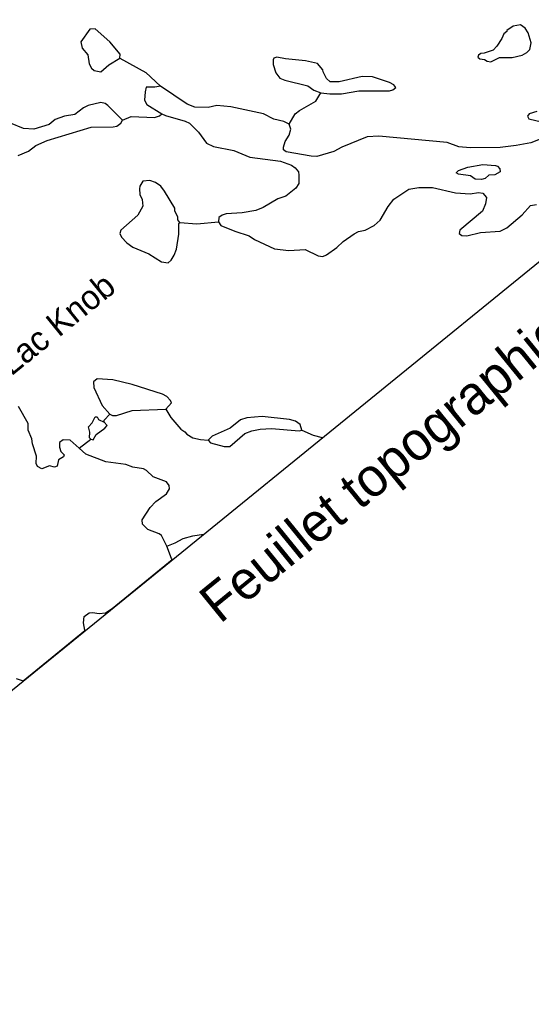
# Model space of a CAD drawing. Extents: x 347059 to 352153, y 6073752 to 6078601.
# Drawn here: x 351007.8 to 351123.8, y 6077139.1 to 6077359.2 of the extents above; entities that cross this region are included whole.
import ezdxf

# ---------------------------------------------------------------- set-up
doc = ezdxf.new("R2010")
doc.units = 0
doc.layers.add('Level 63', color=7, linetype='Continuous')

msp = doc.modelspace()

# ---------------------------------------------------------------- linework, layer by layer
at = {"layer": 'Level 63'}
msp.add_line((351021.38, 6077262.12), (351024, 6077264.16), dxfattribs=at)
msp.add_lwpolyline([(350822.11, 6077057.72), (351218.14, 6077379.8), (350976.59, 6077676.83), (350580.55, 6077354.75)], close=True, dxfattribs=at)
for points in [[(351030.57, 6077350.38), (351030.64, 6077351.32), (351028.25, 6077354.08), (351024.94, 6077357.08), (351023.75, 6077356.96), (351021.75, 6077354.11), (351022.03, 6077352.71), (351023.34, 6077351.14), (351023.63, 6077349.1), (351024.15, 6077348.13), (351024.72, 6077347.61), (351026.23, 6077347.33), (351028.06, 6077348.92), (351030.57, 6077350.38)], [(351119.6, 6077357.65), (351118.16, 6077356.69), (351118.13, 6077356.42), (351117.52, 6077355.95), (351117.07, 6077354.87), (351115.9, 6077353.15), (351115.06, 6077352.26), (351113.06, 6077351.51), (351112.28, 6077351.47), (351111.77, 6077351.08), (351111.58, 6077350.6), (351112.03, 6077350.23), (351113.11, 6077350.09), (351113.7, 6077349.74), (351114.55, 6077349.59), (351116.53, 6077350.57), (351119.35, 6077350.59), (351121.6, 6077351.12), (351122.68, 6077351.72), (351123.39, 6077352.36), (351123.67, 6077353.87), (351122.96, 6077356.14), (351122.31, 6077357.17), (351121.28, 6077357.99), (351119.6, 6077357.65)], [(351030.57, 6077350.38), (351036.44, 6077347.19), (351039.74, 6077344.1)], [(351076.02, 6077342.57), (351078.08, 6077342.32), (351080.76, 6077342.3), (351084.67, 6077343), (351091.62, 6077342.99), (351092.38, 6077343.26), (351093.04, 6077343.77), (351092.57, 6077344.38), (351091.59, 6077344.91), (351087.79, 6077346.15), (351085.39, 6077346.23), (351080.24, 6077345.05), (351078.2, 6077345.08), (351077.33, 6077345.78), (351076.56, 6077347.28), (351076.53, 6077347.74), (351075.3, 6077349.21), (351072.56, 6077349.83), (351068.02, 6077350.26), (351066.11, 6077350.63), (351065.45, 6077350.44), (351065.27, 6077350.05), (351065.27, 6077349.01), (351065.89, 6077347.06), (351066.79, 6077345.91), (351067.91, 6077345.4), (351073.08, 6077344.17), (351074.5, 6077343.17), (351076.02, 6077342.57)], [(351045.83, 6077340.02), (351039.74, 6077344.1), (351038.48, 6077343.84), (351036.53, 6077343.86), (351036.25, 6077342.76), (351036.16, 6077340.9), (351036.67, 6077339.93), (351040.09, 6077337.82), (351040.91, 6077337.4), (351045.35, 6077336.17), (351046.29, 6077335.69), (351048.35, 6077333.65), (351050.18, 6077331.2), (351051.77, 6077330.41), (351056.34, 6077329.52), (351059.97, 6077327.98), (351066.9, 6077327.07), (351069.43, 6077326.21), (351070.26, 6077325.56), (351070.97, 6077324.65), (351071.11, 6077323.95), (351071.05, 6077322.05), (351070.37, 6077320.95), (351068.14, 6077319.14), (351066.34, 6077318.54), (351063, 6077316.59), (351061.33, 6077315.94), (351058.21, 6077315.37), (351054.64, 6077315.18), (351053.74, 6077314.88), (351052.99, 6077314.3), (351052.91, 6077313.35), (351053.4, 6077312.52), (351056.6, 6077311.21), (351059.84, 6077310.17), (351061.01, 6077309.39), (351065.57, 6077307.27), (351068.79, 6077306.87), (351072.51, 6077307.09), (351075.42, 6077305.63), (351076.54, 6077305.54), (351077.35, 6077305.85), (351079.7, 6077307.51), (351081.14, 6077308.88), (351083.59, 6077310.62), (351084.56, 6077311.13), (351086.1, 6077311.44), (351088.1, 6077312.51), (351089.48, 6077313.75), (351091.27, 6077316.84), (351092.57, 6077318.5), (351095.99, 6077320.76)], [(351068.86, 6077335.46), (351070.28, 6077337.79), (351071.24, 6077338.53), (351074.92, 6077340.67), (351076.02, 6077342.57)], [(351031.19, 6077336.39), (351027.87, 6077339.71), (351027.2, 6077340.16), (351026.23, 6077340.37), (351023.37, 6077339.68), (351022.3, 6077339.18), (351020.39, 6077337.69), (351018.02, 6077337.3), (351015.93, 6077336.56), (351014.56, 6077335.41), (351011.05, 6077334.3), (351008.75, 6077334.45), (351005.82, 6077335.73)], [(351125.73, 6077332.1), (351123.63, 6077331.27), (351120.27, 6077330.6), (351116.63, 6077330.19), (351109.89, 6077330.12), (351107.28, 6077330.36), (351104.67, 6077331.32), (351089.16, 6077332.75), (351086.51, 6077332.63), (351080.81, 6077330.29), (351079, 6077329.29), (351075.18, 6077328.17), (351073.86, 6077328.2), (351068.17, 6077329.18), (351067.58, 6077329.62), (351067.57, 6077330.26), (351067.96, 6077331.53), (351068.86, 6077332.96), (351069.26, 6077334.32), (351068.86, 6077335.46), (351067.66, 6077336.07), (351065.45, 6077336.62), (351063.06, 6077337.82), (351055.7, 6077339.38), (351052.52, 6077339.73), (351050.55, 6077339.25), (351047.51, 6077339.31), (351045.83, 6077340.02)], [(351031.19, 6077336.39), (351033.15, 6077337.19), (351038.4, 6077336.99), (351039.54, 6077337.39), (351040.09, 6077337.82)], [(351124.92, 6077338.34), (351123.22, 6077337.83), (351122.83, 6077337.28), (351123.12, 6077336.7), (351126.03, 6077335.98)], [(351007.5, 6077328.38), (351009.89, 6077329.35), (351011.5, 6077330.61), (351014.1, 6077331.74), (351024.08, 6077334.82), (351029.04, 6077334.88), (351029.88, 6077335.05), (351030.74, 6077335.71), (351031.19, 6077336.39)], [(351113.26, 6077323.2), (351112.41, 6077322.94), (351110.96, 6077323.03), (351109.91, 6077323.75), (351107.19, 6077324.14), (351106.68, 6077324.47), (351107.25, 6077324.99), (351109.34, 6077325.73), (351112.74, 6077326.36), (351115.58, 6077326.14), (351116.05, 6077325.94), (351116.57, 6077325.38), (351116.62, 6077324.69), (351115.45, 6077324.02), (351114.07, 6077323.92), (351113.26, 6077323.2)], [(351044.16, 6077313.17), (351043.69, 6077313.77), (351043.68, 6077314.41), (351042.99, 6077315.82), (351042.98, 6077316.45), (351040.69, 6077320.33), (351039.83, 6077321.44), (351038.61, 6077322.27), (351037.35, 6077322.75), (351035.73, 6077322.54), (351035.05, 6077321.44), (351034.97, 6077320.82), (351035.09, 6077319.53), (351035.58, 6077318.38), (351035.76, 6077316.9), (351034.65, 6077314.9), (351030.76, 6077311.47), (351030.57, 6077310.68), (351030.93, 6077309.91), (351032.13, 6077308.58), (351033.51, 6077307.63), (351037.14, 6077306.09), (351040.01, 6077304.27), (351041.48, 6077304.05), (351042.19, 6077304.68), (351042.88, 6077305.78), (351043.41, 6077307.17), (351043.93, 6077310.56), (351043.9, 6077312.88), (351044.16, 6077313.17)], [(351095.99, 6077320.76), (351098.27, 6077321.16), (351101.31, 6077321.1), (351106.52, 6077319.9), (351109.86, 6077319.67), (351111.72, 6077319.98), (351112.74, 6077319.81), (351113.54, 6077318.89), (351113.36, 6077317.46), (351112.65, 6077315.77), (351107.52, 6077311.45), (351107.38, 6077310.7), (351107.96, 6077310.26), (351109.08, 6077310.17), (351112.22, 6077310.91), (351116.67, 6077311.22), (351118.18, 6077311.99), (351121.64, 6077314.92), (351123.54, 6077317.05), (351124.89, 6077317.29)], [(351044.16, 6077313.17), (351047.99, 6077312.92), (351052.91, 6077313.35)], [(351033.31, 6077270.6), (351040.95, 6077270.96), (351042.21, 6077272.35), (351042.01, 6077272.92), (351041.16, 6077273.8), (351040.18, 6077274.33), (351033.37, 6077276.55), (351028.99, 6077277.59), (351025.43, 6077277.81), (351024.57, 6077277.14), (351024.63, 6077275.81), (351026.54, 6077271.8), (351028.25, 6077269.82), (351028.9, 6077269.51), (351029.76, 6077269.54), (351033.31, 6077270.6)], [(351028.81, 6077225.82), (351042.41, 6077236.88), (351042.23, 6077237.11), (351041.17, 6077239.92), (351039.96, 6077242.3), (351039.42, 6077242.69), (351036.86, 6077243.69), (351035.69, 6077244.88), (351035.64, 6077245.89), (351037.44, 6077248.66), (351038.7, 6077250.05), (351041.15, 6077251.79), (351041.83, 6077252.89), (351041.74, 6077253.63), (351041.12, 6077254.52), (351038.08, 6077255.63), (351036.57, 6077257.05), (351035.89, 6077257.41), (351033.48, 6077257.8), (351031.88, 6077258.41), (351027.41, 6077259.05), (351022.85, 6077260.76), (351021.38, 6077262.12), (351019.33, 6077263.93), (351017.75, 6077263.99), (351016.9, 6077263.41), (351016.91, 6077262.36), (351017.23, 6077261.32), (351017.96, 6077260.59), (351017.82, 6077260.16), (351016.64, 6077259.49), (351016.37, 6077258.06), (351015.79, 6077257.77), (351014.65, 6077258.1), (351012.89, 6077257.45), (351011.91, 6077257.98), (351011.63, 6077258.66), (351011.7, 6077260.33), (351010.77, 6077263.08), (351010.64, 6077264.19), (351009.83, 6077266.16), (351009.76, 6077267.71), (351007.64, 6077271.57)], [(351024, 6077264.16), (351023.71, 6077264.43), (351023.74, 6077265.74), (351023.48, 6077266.91), (351024.32, 6077267.81), (351024.94, 6077269.18), (351025.4, 6077269.22), (351025.73, 6077268.58), (351026.98, 6077268.02)], [(351026.98, 6077268.02), (351026.99, 6077268.43), (351028.25, 6077269.82)], [(351040.95, 6077270.96), (351042.12, 6077269.04), (351044.33, 6077266.4), (351045.26, 6077265.83), (351045.69, 6077265.28), (351047.05, 6077264.47), (351048.82, 6077264.07), (351050.53, 6077263.95)], [(351071.73, 6077266.22), (351071.39, 6077267.49), (351070.34, 6077268.21), (351068.98, 6077268.6), (351062.79, 6077269.28), (351059.3, 6077268.99), (351057.88, 6077268.53), (351055.5, 6077266.6), (351051.46, 6077264.83), (351050.53, 6077263.95), (351051.09, 6077263.33), (351054.17, 6077262.49), (351055.44, 6077262.52), (351058.85, 6077265.41), (351060.47, 6077266.03), (351062.34, 6077266.43), (351064.86, 6077266.53), (351071.16, 6077266.01), (351071.73, 6077266.22)], [(351024, 6077264.16), (351024.53, 6077264.01), (351025.22, 6077265.19), (351027.17, 6077266.63), (351027.66, 6077267.25), (351026.98, 6077268.02)], [(351071.73, 6077266.22), (351074.35, 6077265.02), (351076.38, 6077264.51)], [(351041.17, 6077239.92), (351043.08, 6077240.68), (351044.89, 6077241.69), (351047.1, 6077242.28), (351049.49, 6077242.64)], [(351042.41, 6077236.88), (351042.23, 6077237.11), (351041.17, 6077239.92)], [(351007.1, 6077209.93), (351008.65, 6077209.43), (351022.65, 6077220.81), (351022.65, 6077220.9), (351022.36, 6077222.53), (351022.5, 6077224.02), (351023.64, 6077224.83), (351024.38, 6077224.92), (351025.89, 6077224.64), (351027.28, 6077224.83), (351028.81, 6077225.82)], [(351022.65, 6077220.81), (351022.65, 6077220.9), (351022.36, 6077222.53), (351022.5, 6077224.02), (351023.64, 6077224.83), (351024.38, 6077224.92), (351025.89, 6077224.64), (351027.28, 6077224.83), (351028.81, 6077225.82)]]:
    msp.add_lwpolyline(points, dxfattribs=at)

# ---------------------------------------------------------------- texts
for s, height, p in [('Feuillet topographique national : 23J15', 8.71, (351053.22, 6077222.19)), ('Lac Knob', 5.5, (351005.95, 6077278.29))]:
    msp.add_text(s, height=height, rotation=39.1198, dxfattribs=at).set_placement(p)

doc.saveas('drawing.dxf')
